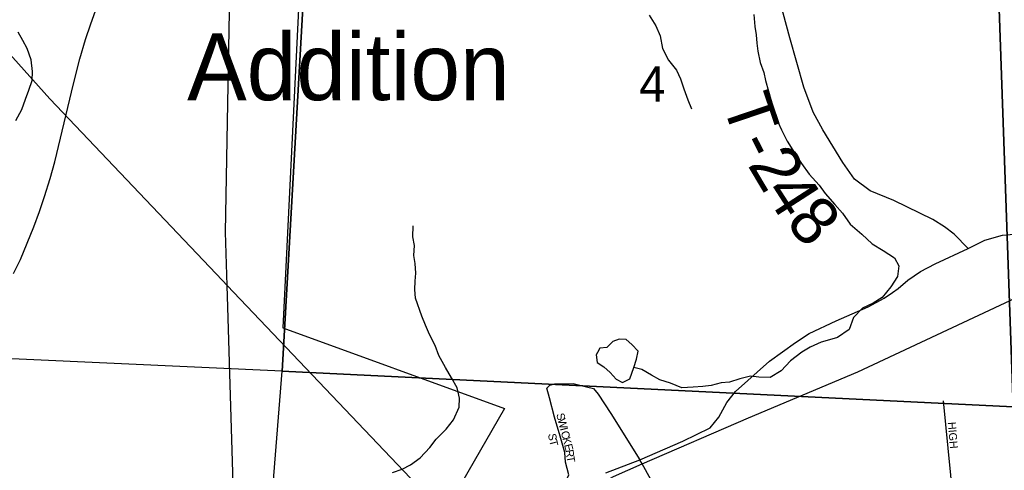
# Model space of a CAD drawing. Extents: x 1624196 to 2029251, y 146837 to 440034.
# Drawn here: x 1860244 to 1866396, y 275678 to 278490 of the extents above; entities that cross this region are included whole.
import ezdxf

# ---------------------------------------------------------------- set-up
doc = ezdxf.new("R2010")
doc.units = 0
for name, color, linetype in [('GM_P_State_Alignment', 7, 'Continuous'), ('GM_X_Corporation', 7, 'Continuous'), ('GM_X_County_Road', 7, 'Continuous'), ('GM_X_Major_River', 7, 'Continuous'), ('GM_X_Minor_Lake', 7, 'Continuous'), ('GM_X_Minor_River', 7, 'Continuous'), ('GM_X_Rail_Line', 7, 'Continuous'), ('GM_X_Section', 7, 'Continuous'), ('GM_X_Section_Text', 7, 'Continuous'), ('GM_X_State_Route', 7, 'Continuous'), ('GM_X_Township_Road', 7, 'Continuous'), ('GM_X_Township_Road_Text', 7, 'Continuous'), ('GM_X_Township_Subdivision', 7, 'Continuous'), ('GM_X_Township_Subdivision_Text', 7, 'Continuous'), ('GM_X_Unincorporated_Text', 7, 'Continuous')]:
    doc.layers.add(name, color=color, linetype=linetype)

msp = doc.modelspace()

# ---------------------------------------------------------------- linework, layer by layer
at = {"layer": 'GM_P_State_Alignment'}
for points in [[(1861544.2, 276696.4), (1861540.1, 276831.7), (1861529.9, 277163.6), (1861580.2, 279919), (1861612.6, 280380.9), (1861665.1, 281130), (1861669.1, 281144.2), (1861790.1, 281575.9), (1861836.7, 281721.8), (1862029, 282324.9), (1862672.3, 284178.2), (1863400.7, 284922.3), (1863628.9, 285155.2), (1864060.2, 285560.8)], [(1861511.5, 276861.7), (1860431.7, 277996.1), (1859184.2, 279387.8), (1858872.6, 279744.1), (1858597.3, 280059.1), (1857442.1, 281556), (1857427.3, 281575.2), (1856929.1, 281940.1)], [(1861874.5, 274742.2), (1862064.2, 274850.8), (1862146.9, 274886.5), (1862221.6, 274909.2), (1862468.2, 274980.7), (1862817.1, 275066.7), (1863068.6, 275126.7), (1863088.2, 275172.1), (1863130.1, 275268.7), (1863334.2, 275354.2), (1863587.6, 275464), (1863663, 275496.7), (1863811.4, 275560.9), (1863954.5, 275640.5), (1864133.3, 275718.1), (1864797.6, 276006.3), (1865481.6, 276292.6), (1866467.8, 276753.9), (1867040.5, 277072), (1867214.4, 277178.7)], [(1863898.1, 269471.8), (1863484.2, 269845.5), (1863333.4, 269996.3), (1863288.2, 270252.8), (1863363.6, 270614.7), (1863507.6, 270830.7), (1863654.2, 271050.8), (1863839, 271327.9), (1864027.2, 271610.2), (1864223.2, 272077.7), (1864298.6, 272605.6), (1864339.8, 273293.4), (1863898.8, 274237.3), (1863145.5, 275106.1), (1863088.2, 275172.1), (1862766.3, 275543.4), (1861540.1, 276831.7), (1861511.5, 276861.7)], [(1862030.5, 272820.3), (1861901, 273014.7), (1861847.1, 273164.9), (1861797.2, 273304.1), (1861684, 273955.2), (1861613.4, 274480.2), (1861611.7, 274493.1), (1861544.2, 276696.4)]]:
    msp.add_lwpolyline(points, dxfattribs=at)
at = {"layer": 'GM_X_Corporation'}
msp.add_lwpolyline([(1857933.2, 281887.5), (1862096.6, 281749.8), (1862080.9, 280892.8), (1862002.9, 278896.9), (1861887.1, 276567.8), (1863273.4, 276063.1), (1862625, 274940.1), (1862578.2, 274925.5), (1862426.8, 274878.5), (1862073.6, 274768.6), (1861871.7, 274705.9), (1861787.8, 274634), (1861723.6, 273388.7), (1861737.3, 271615), (1861550.4, 272074.5), (1861362.2, 272391.6), (1861052.9, 272768.8), (1860525.5, 273440.9), (1860307.4, 273752), (1860232.5, 273857.7)], dxfattribs=at)
at = {"layer": 'GM_X_County_Road'}
msp.add_lwpolyline([(1866587.5, 274314.3), (1866329.7, 274381.2), (1866213, 274415.2), (1865979.6, 274487.5), (1865942.7, 274500.9), (1865817.1, 274602.8), (1865611.5, 274776.4), (1865413.7, 274955), (1865229.6, 275097.1), (1865169.3, 275136.9), (1865121.5, 275153.5), (1864979.4, 275167.7), (1864916.2, 275171.8), (1864881, 275174.3), (1864814.2, 275169.9), (1864689.5, 275174.3), (1864578.1, 275171.3), (1864495, 275175.8), (1864444.5, 275192.1), (1864394.1, 275248.6), (1864133.3, 275718.1), (1864119.1, 275743.6)], dxfattribs=at)
at = {"layer": 'GM_X_Major_River'}
msp.add_lwpolyline([(1860219.5, 277860.8), (1860257.3, 277929), (1860279.1, 277993.2), (1860301, 278049.3), (1860320.8, 278111.4), (1860322.7, 278167.5), (1860314.5, 278239.6), (1860290.4, 278309.7), (1860262.3, 278359.7), (1860234.2, 278411.7)], dxfattribs=at)
at = {"layer": 'GM_X_Minor_Lake'}
for points in [[(1864081.3, 276318.7), (1864097.6, 276370.7), (1864107.8, 276420.8), (1864068, 276463.1), (1864034, 276495.3), (1863990, 276497.5), (1863949.9, 276481.7), (1863911.6, 276443.8), (1863869.6, 276440), (1863854.1, 276413.1)], [(1863854.1, 276413.1), (1863845.3, 276398), (1863851.1, 276351.8), (1863893.1, 276323.6), (1863933, 276289.3), (1863970.9, 276247), (1864010.8, 276226.8), (1864057, 276248.6), (1864081.3, 276318.7)]]:
    msp.add_lwpolyline(points, dxfattribs=at)
at = {"layer": 'GM_X_Minor_River'}
for points in [[(1864830.2, 278522.7), (1864837.9, 278448.5), (1864845.7, 278396.3), (1864849.5, 278344.2), (1864855.3, 278294), (1864871, 278223.8), (1864892.7, 278161.5), (1864904.5, 278111.3), (1864922.3, 278043.1), (1864936.1, 277992.9), (1864957.8, 277922.6), (1864981.5, 277852.3), (1865003.3, 277802.1), (1865039.1, 277731.8), (1865084.8, 277659.4), (1865128.6, 277593), (1865176.4, 277526.6), (1865238.1, 277458.1), (1865276, 277405.8), (1865337.8, 277337.4), (1865385.6, 277283), (1865433.4, 277214.6), (1865505.2, 277152.1), (1865571, 277091.7), (1865639, 277049.3), (1865708.9, 277004.8), (1865736.7, 276954.6), (1865728.4, 276888.5), (1865686, 276822.5), (1865633.7, 276756.5), (1865577.4, 276720.7), (1865509.2, 276689), (1865452.8, 276631.1), (1865426.4, 276557), (1865354.1, 276507.2), (1865304, 276491.4), (1865251.8, 276477.6), (1865183.6, 276445.9), (1865131.4, 276416), (1865061, 276362.2), (1865002.7, 276298.3), (1864932.4, 276256.6), (1864862.3, 276258.9), (1864810.2, 276265.1), (1864744, 276249.4), (1864677.9, 276227.7), (1864627.8, 276223.9), (1864563.6, 276208.1), (1864511.5, 276200.4), (1864451.4, 276196.6), (1864381.2, 276193), (1864309.3, 276221.4), (1864243.2, 276241.7), (1864191.3, 276272), (1864131.4, 276306.4), (1864081.3, 276318.7)], [(1864177.2, 278517.8), (1864219, 278451.4), (1864244.8, 278389.1), (1864260.4, 278310.8), (1864298.2, 278238.5), (1864348, 278176.1), (1864371.8, 278121.8), (1864393.5, 278059.6), (1864419.3, 277989.3), (1864441, 277933.1)], [(1862572.1, 275664), (1862634.3, 275685.8), (1862684.5, 275711.6), (1862746.8, 275755.5), (1862807.2, 275821.3), (1862845.5, 275873.3), (1862907.9, 275935.2), (1862954.2, 275993.1), (1862988.6, 276073.1), (1862990.8, 276127.3), (1862977.1, 276193.5), (1862941.3, 276255.8), (1862903.6, 276320.1), (1862861.8, 276394.5), (1862840.1, 276456.8), (1862804.3, 276525.1), (1862778.5, 276583.4), (1862756.7, 276639.6), (1862717.2, 276752.1), (1862713.4, 276806.3), (1862715.7, 276858.4), (1862717.9, 276908.5), (1862714.1, 276968.7), (1862706.3, 277018.8), (1862710.6, 277081), (1862700.8, 277135.1), (1862701.2, 277203.3)]]:
    msp.add_lwpolyline(points, dxfattribs=at)
at = {"layer": 'GM_X_Rail_Line'}
msp.add_lwpolyline([(1860205.6, 276906.3), (1860247.8, 276994.6), (1860290, 277094.7), (1860332.2, 277197), (1860367.4, 277292.4), (1860398.6, 277386.2), (1860433, 277498.7), (1860463.5, 277602.6), (1860579.9, 278090.3), (1860619.8, 278245), (1860654.2, 278366.2), (1860688.6, 278464.6), (1860717.5, 278545.1)], dxfattribs=at)
at = {"layer": 'GM_X_Section'}
for points in [[(1855574.9, 282007.2), (1856638.9, 282002.1), (1862193.5, 281747.1), (1861882.7, 276297.8), (1854942.8, 276613.9)], [(1862193.5, 281747.1), (1866257.2, 281575.1), (1866452.3, 276073.9), (1861882.7, 276297.8)], [(1866257.2, 281575.1), (1872946.7, 281242), (1872577.6, 275738.7), (1866452.3, 276073.9)]]:
    msp.add_lwpolyline(points, close=True, dxfattribs=at)
msp.add_lwpolyline([(1861571.6, 272380.8), (1861882.7, 276297.8), (1866452.3, 276073.9)], dxfattribs=at)
at = {"layer": 'GM_X_State_Route'}
msp.add_lwpolyline([(1863905.3, 275662.5), (1864119.1, 275743.6), (1864276.1, 275812.6), (1864386.9, 275859.2), (1864558.5, 275944), (1864611.5, 276009.7), (1864662.4, 276100.8), (1864715.4, 276170.8), (1864929.4, 276359.4), (1865090.5, 276475.6), (1865177, 276532.6), (1865346.3, 276609.9), (1865546, 276698.6), (1865646.2, 276752.9), (1865697.3, 276787.8), (1865732.7, 276812.4), (1865793.3, 276864.3), (1865872.4, 276918), (1865963.9, 276965.6), (1866170.6, 277062.7), (1866275.2, 277114.9), (1866383.8, 277146.1), (1866554.9, 277161)], dxfattribs=at)
at = {"layer": 'GM_X_Township_Road'}
msp.add_lwpolyline([(1866170.6, 277062.7), (1866082.2, 277151.2), (1866021.5, 277197.1), (1865949, 277244), (1865706.7, 277362), (1865556.9, 277421.4), (1865460.8, 277494.9), (1865387.3, 277599.5), (1865263, 277803), (1865200.9, 277913.3), (1865144.3, 278068.7), (1865056.8, 278376.8), (1864966.3, 278710.4)], dxfattribs=at)
at = {"layer": 'GM_X_Township_Subdivision'}
for points in [[(1863539.6, 275360.6), (1863587.6, 275464), (1863641.4, 275579.7), (1863674.1, 275650.4), (1863653.5, 275729.8), (1863650, 275788.5), (1863620.7, 275892), (1863586.2, 276009.3), (1863553.4, 276130.1), (1863537.9, 276190.5), (1863556.8, 276209.5), (1863587.9, 276218.1), (1863701.8, 276219.8), (1863736.2, 276211.2), (1863784.5, 276199.1), (1863829.4, 276188.8), (1863858.7, 276154.3), (1863938, 276031.8), (1864119.1, 275743.6)], [(1866091.7, 275351.9), (1866015.5, 276111.1)]]:
    msp.add_lwpolyline(points, dxfattribs=at)

# ---------------------------------------------------------------- texts
at = {"layer": 'GM_X_Section_Text'}
msp.add_text('4', height=221, rotation=0.00001, dxfattribs=at).set_placement((1864114.8, 277979))
at = {"layer": 'GM_X_Township_Road_Text'}
for s, rotation, p in [('T', 288.71616, (1864632.3, 277969.8)), ('-', 296.77571, (1864722, 277714.8)), ('2', 300.79296, (1864788.6, 277584.7)), ('4', 302.75564, (1864889.1, 277416.5)), ('8', 312.51212, (1865023.1, 277217))]:
    msp.add_text(s, height=300, rotation=rotation, dxfattribs=at).set_placement(p)
at = {"layer": 'GM_X_Township_Subdivision_Text'}
for s, rotation, p in [('S', 284.3278, (1863595.8, 276028.2)), ('W', 284.3395, (1863604.6, 275994.1)), ('I', 284.35075, (1863618.7, 275938.6)), ('HIGH', 274.89645, (1866042.5, 275978)), ('S', 277.12163, (1863545.5, 275905.2)), ('C', 284.33073, (1863624.2, 275917.3)), ('K', 284.34997, (1863634, 275878.9)), ('T', 284.34777, (1863551.1, 275863.5)), ('E', 284.3278, (1863644.9, 275836.3)), ('R', 279.04712, (1863653.3, 275803.4)), ('T', 279.54371, (1863659.6, 275763.8))]:
    msp.add_text(s, height=50, rotation=rotation, dxfattribs=at).set_placement(p)
at = {"layer": 'GM_X_Unincorporated_Text'}
msp.add_text('Addition', height=417, rotation=0.00001, dxfattribs=at).set_placement((1861290, 277987.8))

doc.saveas('drawing.dxf')
